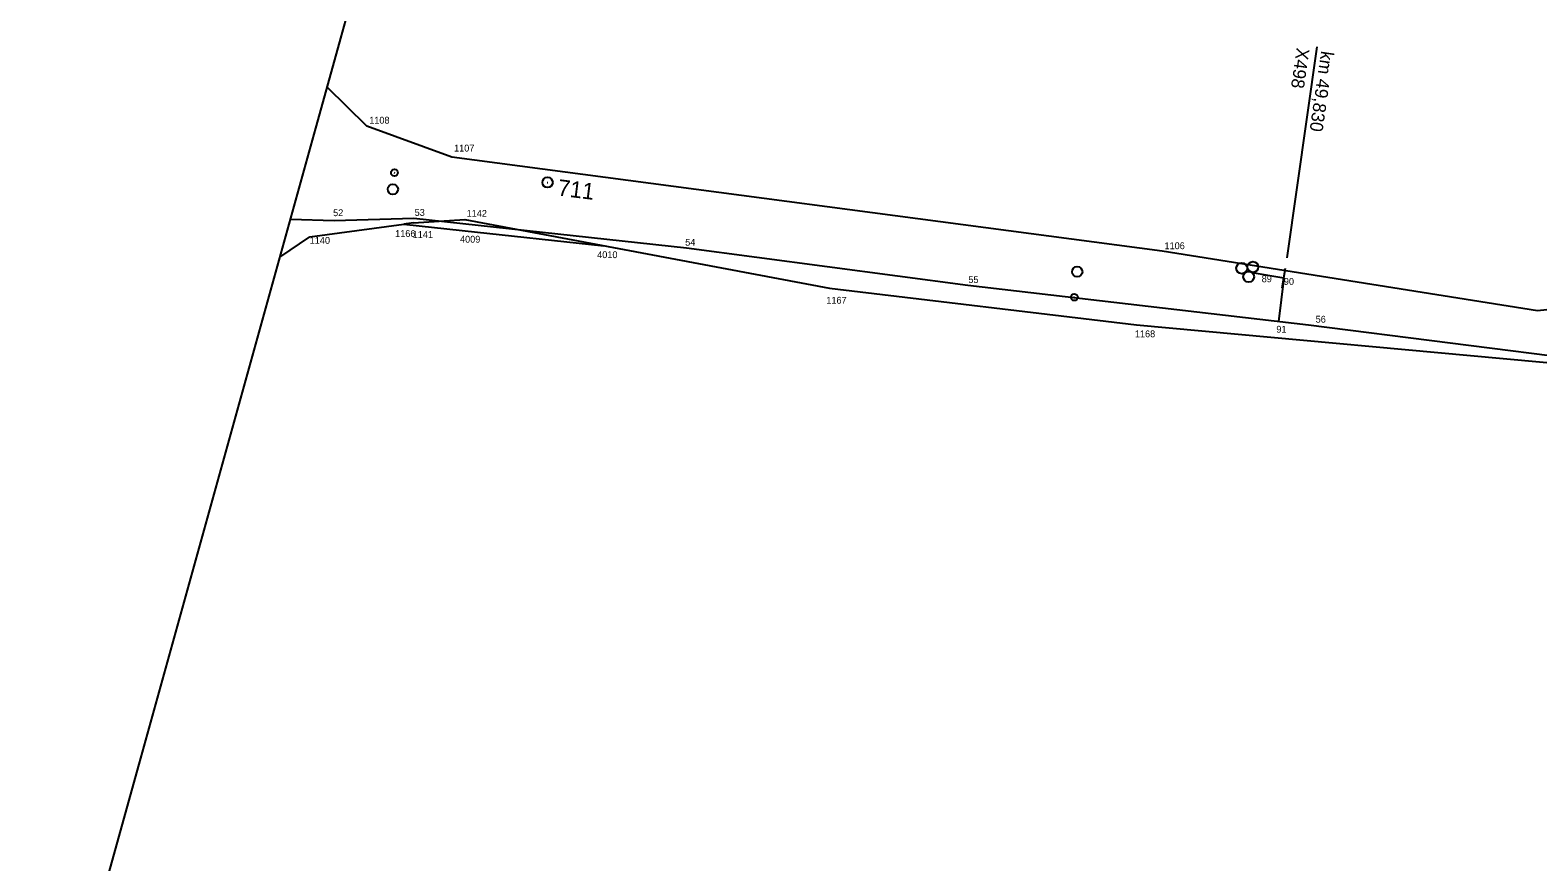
# Model space of a CAD drawing. Extents: x -678084 to -677195, y -1006706 to -1006195.
# Drawn here: x -678084.3 to -677863.3, y -1006437.6 to -1006315.8 of the extents above; entities that cross this region are included whole.
import ezdxf

# ---------------------------------------------------------------- set-up
doc = ezdxf.new("R2010")
doc.units = 0
for name, color, linetype in [('Dočasný zábor - do 1 roku', 7, 'Continuous'), ('Dočasný zábor_body', 7, 'Continuous'), ('rozpiska - rámy', 7, 'Continuous'), ('SSZT nové - lomové body', 7, 'Continuous'), ('SSZT_nové', 7, 'Continuous'), ('Stávající ŽBP', 7, 'Continuous'), ('SŽDC', 7, 'Continuous'), ('SŽDC - body', 7, 'Continuous'), ('Vrstva 7', 7, 'Continuous')]:
    doc.layers.add(name, color=color, linetype=linetype)

msp = doc.modelspace()

# ---------------------------------------------------------------- linework, layer by layer
at = {"layer": 'Dočasný zábor - do 1 roku'}
for p, q in [((-678029.55, -1006344.22), (-678021.01, -1006345.14)), ((-678021.01, -1006345.14), (-678000.24, -1006347.39))]:
    msp.add_line(p, q, dxfattribs=at)
at = {"layer": 'Dočasný zábor_body'}
for p, q in [((-678021.01, -1006345.14), (-678021.01, -1006345.14)), ((-678000.24, -1006347.39), (-678000.24, -1006347.39))]:
    msp.add_line(p, q, dxfattribs=at)
at = {"layer": 'rozpiska - rámy'}
msp.add_line((-678084.34, -1006480.66), (-678004.72, -1006194.53), dxfattribs=at)
at = {"layer": 'SSZT nové - lomové body'}
for p, q in [((-678028.1, -1006343.37), (-678028.1, -1006343.37)), ((-678039.76, -1006343.69), (-678039.76, -1006343.69)), ((-677988.11, -1006347.69), (-677988.11, -1006347.69)), ((-677903.81, -1006351.73), (-677903.81, -1006351.73)), ((-677900.56, -1006352.12), (-677900.56, -1006352.12)), ((-677946.88, -1006353.16), (-677946.88, -1006353.16)), ((-677901.34, -1006358.47), (-677901.34, -1006358.47)), ((-677896.95, -1006358.97), (-677896.95, -1006358.97))]:
    msp.add_line(p, q, dxfattribs=at)
at = {"layer": 'SSZT_nové'}
for p, q in [((-677895.71, -1006318.24), (-677900.14, -1006349.16)), ((-677905.23, -1006351.31), (-677900.56, -1006352.09)), ((-677900.56, -1006352.12), (-677901.34, -1006358.47)), ((-677900.79, -1006353.55), (-677900.34, -1006350.68))]:
    msp.add_line(p, q, dxfattribs=at)
msp.add_lwpolyline([(-678046.18, -1006343.51), (-678039.76, -1006343.69), (-678028.1, -1006343.37), (-677988.11, -1006347.69), (-677946.88, -1006353.16), (-677896.95, -1006358.97), (-677855.43, -1006364.26), (-677800.81, -1006372.62), (-677763.07, -1006378.4), (-677730.99, -1006381.64), (-677703.96, -1006383), (-677678.22, -1006388.09), (-677650.5, -1006395.33), (-677540.71, -1006433.07)], dxfattribs=at)
for centre in [(-677906.74, -1006350.69), (-677905.1, -1006350.5), (-677905.72, -1006351.93)]:
    msp.add_circle(centre, 0.792, dxfattribs=at)
at = {"layer": 'Stávající ŽBP'}
msp.add_line((-678008.55, -1006338.11), (-678008.45, -1006338.12), dxfattribs=at)
msp.add_circle((-678008.5, -1006338.11), 0.756, dxfattribs=at)
at = {"layer": 'SŽDC'}
for p, q in [((-678034.98, -1006329.89), (-678040.79, -1006324.16)), ((-678022.51, -1006334.41), (-678034.98, -1006329.89)), ((-677918.4, -1006348.18), (-678022.51, -1006334.41)), ((-678043.36, -1006346.1), (-678029.55, -1006344.22)), ((-678028.13, -1006344.03), (-678029.55, -1006344.22)), ((-678028.13, -1006344.03), (-678020.64, -1006343.54)), ((-678020.64, -1006343.54), (-677967.17, -1006353.62)), ((-678047.72, -1006349.06), (-678043.36, -1006346.1)), ((-677863.38, -1006356.93), (-677918.4, -1006348.18)), ((-677967.17, -1006353.62), (-677922.14, -1006358.97)), ((-677845.59, -1006355.04), (-677863.38, -1006356.93)), ((-677922.14, -1006358.97), (-677854.94, -1006365.15))]:
    msp.add_line(p, q, dxfattribs=at)
at = {"layer": 'SŽDC - body'}
for p, q in [((-678034.98, -1006329.89), (-678034.98, -1006329.89)), ((-678022.51, -1006334.41), (-678022.51, -1006334.41)), ((-678029.55, -1006344.22), (-678029.55, -1006344.22)), ((-678028.13, -1006344.03), (-678028.13, -1006344.03)), ((-678020.64, -1006343.54), (-678020.64, -1006343.54)), ((-678043.36, -1006346.1), (-678043.36, -1006346.1)), ((-677918.4, -1006348.18), (-677918.4, -1006348.18)), ((-677967.17, -1006353.62), (-677967.17, -1006353.62)), ((-677863.38, -1006356.93), (-677863.38, -1006356.93)), ((-677922.14, -1006358.97), (-677922.14, -1006358.97))]:
    msp.add_line(p, q, dxfattribs=at)
at = {"layer": 'Vrstva 7'}
for p, q in [((-678030.99, -1006336.68), (-678030.89, -1006336.69)), ((-677931.33, -1006354.92), (-677931.23, -1006354.93))]:
    msp.add_line(p, q, dxfattribs=at)
for centre, radius in [((-678030.94, -1006336.69), 0.5), ((-678031.17, -1006339.12), 0.75), ((-677930.85, -1006351.19), 0.75), ((-677931.28, -1006354.93), 0.5)]:
    msp.add_circle(centre, radius, dxfattribs=at)

# ---------------------------------------------------------------- texts
at = {"layer": 'Dočasný zábor_body'}
for s, p in [('4009', (-678021.33, -1006346.93)), ('4010', (-678001.22, -1006349.2))]:
    msp.add_text(s, height=1, dxfattribs=at).set_placement(p)
at = {"layer": 'SSZT nové - lomové body'}
for s, p in [('52', (-678039.93, -1006343.05)), ('53', (-678027.98, -1006343.01)), ('54', (-677988.32, -1006347.38)), ('55', (-677946.81, -1006352.85)), ('89', (-677903.81, -1006352.73)), ('90', (-677900.56, -1006353.12)), ('56', (-677895.9, -1006358.65)), ('91', (-677901.66, -1006360.12))]:
    msp.add_text(s, height=1, dxfattribs=at).set_placement(p)
at = {"layer": 'SSZT_nové'}
for s, p in [('X498', (-677898.67, -1006318.33)), ('km 49,830', (-677895.09, -1006318.79))]:
    msp.add_text(s, height=1.9, rotation=261.7542, dxfattribs=at).set_placement(p)
at = {"layer": 'Stávající ŽBP'}
msp.add_text('711', height=2.4, rotation=352.972, dxfattribs=at).set_placement((-678007.1, -1006340.02))
at = {"layer": 'SŽDC - body'}
for s, p in [('1108', (-678034.64, -1006329.5)), ('1107', (-678022.2, -1006333.59)), ('1142', (-678020.36, -1006343.15)), ('1166', (-678030.84, -1006346.1)), ('1141', (-678028.27, -1006346.25)), ('1140', (-678043.36, -1006347.1)), ('1106', (-677918.06, -1006347.89)), ('1167', (-677967.63, -1006355.87)), ('1168', (-677922.4, -1006360.79))]:
    msp.add_text(s, height=1, dxfattribs=at).set_placement(p)

doc.saveas('drawing.dxf')
